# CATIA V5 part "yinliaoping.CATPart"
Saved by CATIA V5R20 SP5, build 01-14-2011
Part number: 饮料瓶
Material "Grey Blue": density 7860 kg/m3, Young's modulus 2e+11 Pa, Poisson ratio 0.266
Bounding box of the stored display mesh (mm): x -25 to 26, y -25 to 25, z 0 to 110
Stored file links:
  E:\10511725\bottle.CATPart
  C:\Program Files\Dassault Systemes\B20\intel_a\startup\materials\Catalog.CATMaterial
  C:\Program Files\Dassault Systemes\B20\intel_a\startup\materials\yellow_env_512x512.jpg
  C:\Program Files\Dassault Systemes\B20\intel_a\startup\materials\red_env_512x512.jpg
  C:\Program Files\Dassault Systemes\B20\intel_a\startup\materials\alpin_fir.jpg
  C:\Program Files\Dassault Systemes\B20\intel_a\startup\materials\brushed_metal2.jpg
  C:\Program Files\Dassault Systemes\B20\intel_a\startup\materials\blue_env_512x512.jpg
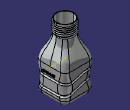
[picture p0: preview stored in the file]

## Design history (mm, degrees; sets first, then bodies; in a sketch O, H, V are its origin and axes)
Set1
  Sketch1 on xy-plane, origin (0, 0, 0), H (1, 0, 0), V (0, 1, 0)
    point P1 (0, 0)
    line L1 (25, 25) -> (25, -25)
    line L2 (25, -25) -> (-25, -25)
    line L3 (-25, -25) -> (-25, 25)
    line L4 (-25, 25) -> (25, 25)
    length L1 = 50
    length L4 = 50
    coincidence: P1 V, P1 H
    vertical: L1 V, L3 V
    horizontal: L2 H, L4 H
    equidistance: L1 L3 P1, L2 L4 P1
  Sketch2 on face of Pad1 from Sketch1.L2, origin (0, -25, 0), H (1, 0, 0), V (0, 0, 1)
    spline S1 through (-48.822, 0) (-10.1473, 23.8211) (12.744, 16.6738) (57.9052, 27.3431)
    point P1 (-48.822, 0)
    coincidence: P1 H
  Extrude1: Element1 Sketch2, Lim1 60, Lim2 60
  MultiSel1: CommonCtxFeats ({extract ExtractElem face of Pad1 from Sketch1.L4}; {extract ExtractElem face of Fillet1}; {extract ExtractElem face of Pad1 from Sketch1.L3}; {extract ExtractElem face of Fillet1}; {extract ExtractElem face of Pad1 from Sketch1.L2}; {extract ExtractElem face of Fillet1}; {extract ExtractElem face of Pad1 from Sketch1.L1}; {extract ExtractElem face of Fillet1})
  Sketch3 on face of Pad1 from Sketch1.L2, origin (0, -25, 0), H (1, 0, 0), V (0, 0, 1)
    spline S1 through (-34.0063, 29.5181) (-13.3283, 38.6631) (8.749, 33.2381) (34.5577, 36.0281)
  Extrude2: Element1 Sketch3, Lim1 60, Lim2 60
  MultiSel2: CommonCtxFeats ({extract ExtractElem face of Pad1 from Sketch1.L2}; {extract ExtractElem face of Fillet1}; {extract ExtractElem face of Pad1 from Sketch1.L1}; {extract ExtractElem face of Fillet1}; {extract ExtractElem face of Pad1 from Sketch1.L4}; {extract ExtractElem face of Fillet1}; {extract ExtractElem face of Pad1 from Sketch1.L3}; {extract ExtractElem face of Fillet1})
  Join1: Elements ({intersect ToIntersect1 {extract ExtractElem face of Pad1 from Sketch1.L2}, ToIntersect2 Extrude2}; {intersect ToIntersect1 {extract ExtractElem face of Fillet1}, ToIntersect2 Extrude2}; {intersect ToIntersect1 {extract ExtractElem face of Pad1 from Sketch1.L1}, ToIntersect2 Extrude2}; {intersect ToIntersect1 {extract ExtractElem face of Fillet1}, ToIntersect2 Extrude2}; {intersect ToIntersect1 {extract ExtractElem face of Pad1 from Sketch1.L4}, ToIntersect2 Extrude2}; {intersect ToIntersect1 {extract ExtractElem face of Fillet1}, ToIntersect2 Extrude2}; {intersect ToIntersect1 {extract ExtractElem face of Pad1 from Sketch1.L3}, ToIntersect2 Extrude2}; {intersect ToIntersect1 {extract ExtractElem face of Fillet1}, ToIntersect2 Extrude2})
  Join2: Elements {intersect ToIntersect1 Fillet1, ToIntersect2 Extrude1}
  Join3: Elements ({intersect ToIntersect1 {extract ExtractElem face of Pad1 from Sketch1.L4}, ToIntersect2 Extrude1}; {intersect ToIntersect1 {extract ExtractElem face of Fillet1}, ToIntersect2 Extrude1}; {intersect ToIntersect1 {extract ExtractElem face of Pad1 from Sketch1.L3}, ToIntersect2 Extrude1}; {intersect ToIntersect1 {extract ExtractElem face of Fillet1}, ToIntersect2 Extrude1}; {intersect ToIntersect1 {extract ExtractElem face of Pad1 from Sketch1.L2}, ToIntersect2 Extrude1}; {intersect ToIntersect1 {extract ExtractElem face of Fillet1}, ToIntersect2 Extrude1}; {intersect ToIntersect1 {extract ExtractElem face of Pad1 from Sketch1.L1}, ToIntersect2 Extrude1}; {intersect ToIntersect1 {extract ExtractElem face of Fillet1}, ToIntersect2 Extrude1})
  Plane1: type Normal, Curve Join3, RefPoint vertex [face of MultiSel1 | face of MultiSel1]
  Circle1: type CtrRad, Start 0, End 180, Center vertex [face of MultiSel1 | face of MultiSel1], Support Plane1, Radius 2, FirstDirection (0, 1, 0)
  Plane2: type Normal, Curve Join1, RefPoint vertex [face of MultiSel2 | face of MultiSel2]
  Circle2: type CtrRad, Start 0, End 180, Center vertex [face of MultiSel2 | face of MultiSel2], Support Plane2, Radius 2, FirstDirection (0, 1, 0)
Body1 (main body), material "Grey Blue"
  Pad1: profile Sketch1, direction (0, 0, 1), length 50
  Fillet1: on edge [face of Pad1 from Sketch1.L4 | face of Pad1 from Sketch1.L1]; edge [face of Pad1 from Sketch1.L3 | face of Pad1 from Sketch1.L4]; edge [face of Pad1 from Sketch1.L1 | face of Pad1 from Sketch1.L2]; edge [face of Pad1 from Sketch1.L2 | face of Pad1 from Sketch1.L3]
  Fillet2: radius 8, on start face of Pad1
  Plane3: type Offset, RefPlane end face of Pad1, Offset 40, reversed
  Sketch4 on Plane3, origin (0, 0, 90), H (1, 0, 0), V (0, -1, 0)
    circle A1 centre (0, 0) radius 15
  Pad2: profile Sketch4, direction (0, 0, 1), length 20
  Sketch5 on start face of Pad2, origin (0, 0, 90), H (1, 0, 0), V (0, -1, 0)
    point P1 (15, 0)
    distance P1 V = 15
    coincidence: P1 H
  Sketch6 on end face of Pad1, origin (0, 0, 50), H (1, 0, 0), V (0, 1, 0)
    point P1 (25, 0)
    distance P1 V = 25
    coincidence: P1 H
  Sketch7 on end face of Pad1, origin (0, 0, 50), H (1, 0, 0), V (0, 1, 0)
  Loft1: solid, Sections ({boundary Boundary {extract ExtractElem end face of Pad1}}; {boundary Boundary {extract ExtractElem start face of Pad2}}), StartFace end face of Pad1, EndFace start face of Pad2
  Slot1: profile Circle2, centre curve Join1
  Slot2: profile Circle1, centre curve Join3
  Shell1: ExtOffset 0, Face end face of Pad2, IntOffset 1
  Helix1: Direction Z axis, RefPoint Sketch5, Pitch 3, Height 18, TaperAngle 0
  Point1: type OnCurve, Support Helix1, RefPoint vertex of Helix1, Length -5
  Line1: type PtDir, RefPoint vertex of Helix1, Direction (1, 0, 0), Start 0, End 10
  Connect1: Curve1 Line1, Point1 vertex of Line1, Tension1 1, Curve2 Helix1, Point2 Point1, Tension2 1
  Point2: type OnCurve, Support Connect1, RefPoint Sketch5, Length -5
  Line2: type PtDir, RefPoint Sketch5, Direction (1, 0, 0), Start 0, End 10
  Connect2: Curve1 Line2, Point1 vertex of Line2, Tension1 1, Curve2 Connect1, Point2 Point2, Tension2 1
  Plane4: type Normal, Curve Connect2, RefPoint vertex of Connect1
  Circle3: type CtrRad, Start 0, End 180, Center vertex of Connect1, Support Plane4, Radius 1, FirstDirection (0, -1, 0)
  Rib1: profile Circle3, centre curve Connect2
  Body2
    Sketch8 on Plane3, origin (0, 0, 90), H (1, 0, 0), V (0, -1, 0)
      circle A1 centre (0, 0) radius 14
      polyline C1
      polyline C2
      polyline C3
      polyline C4
      polyline C5
      polyline C6
      polyline C7
      polyline C8
      polyline C9
      polyline C10
      polyline C11
      radius A1 = 14
    Pad3: profile Sketch8, direction (0, 0, -1), length 20, mirrored extent
  Remove1: tool Body2
  Sketch9 on face of Pad1 from Sketch1.L1, origin (25, 0, 0), H (0, 1, 0), V (0, 0, 1)
    polyline C1
    polyline C2
    polyline C3
    polyline C4
    polyline C5
    polyline C6
    polyline C7
    polyline C8
    polyline C9
    polyline C10
    polyline C11
  Pad4: profile Sketch9, direction (1, 0, 0), length 1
